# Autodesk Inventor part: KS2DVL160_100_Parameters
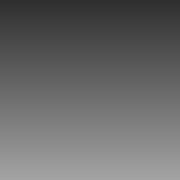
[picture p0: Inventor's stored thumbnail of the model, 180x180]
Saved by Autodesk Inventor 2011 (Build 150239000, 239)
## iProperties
Created: 2010-11
Document SubType Name: Modeling
Designer: TB
Density: 1 g/cm^3
Slaglengde: 100,000 mm
Vinkel_Minusport: 0.00 deg
Forlengelse_rør: 0.000 mm
Minusport2: 180.00 deg
Author: TB
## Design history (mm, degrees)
other parameters: "Slaglengde" = 100 [user parameter], "Forlengelse_rør" = 0 [user parameter], "Vinkel_Minusport" = 0 deg [user parameter], "Minusport2" = 180 deg [user parameter]
